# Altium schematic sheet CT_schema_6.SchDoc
size 287 x 160 mm
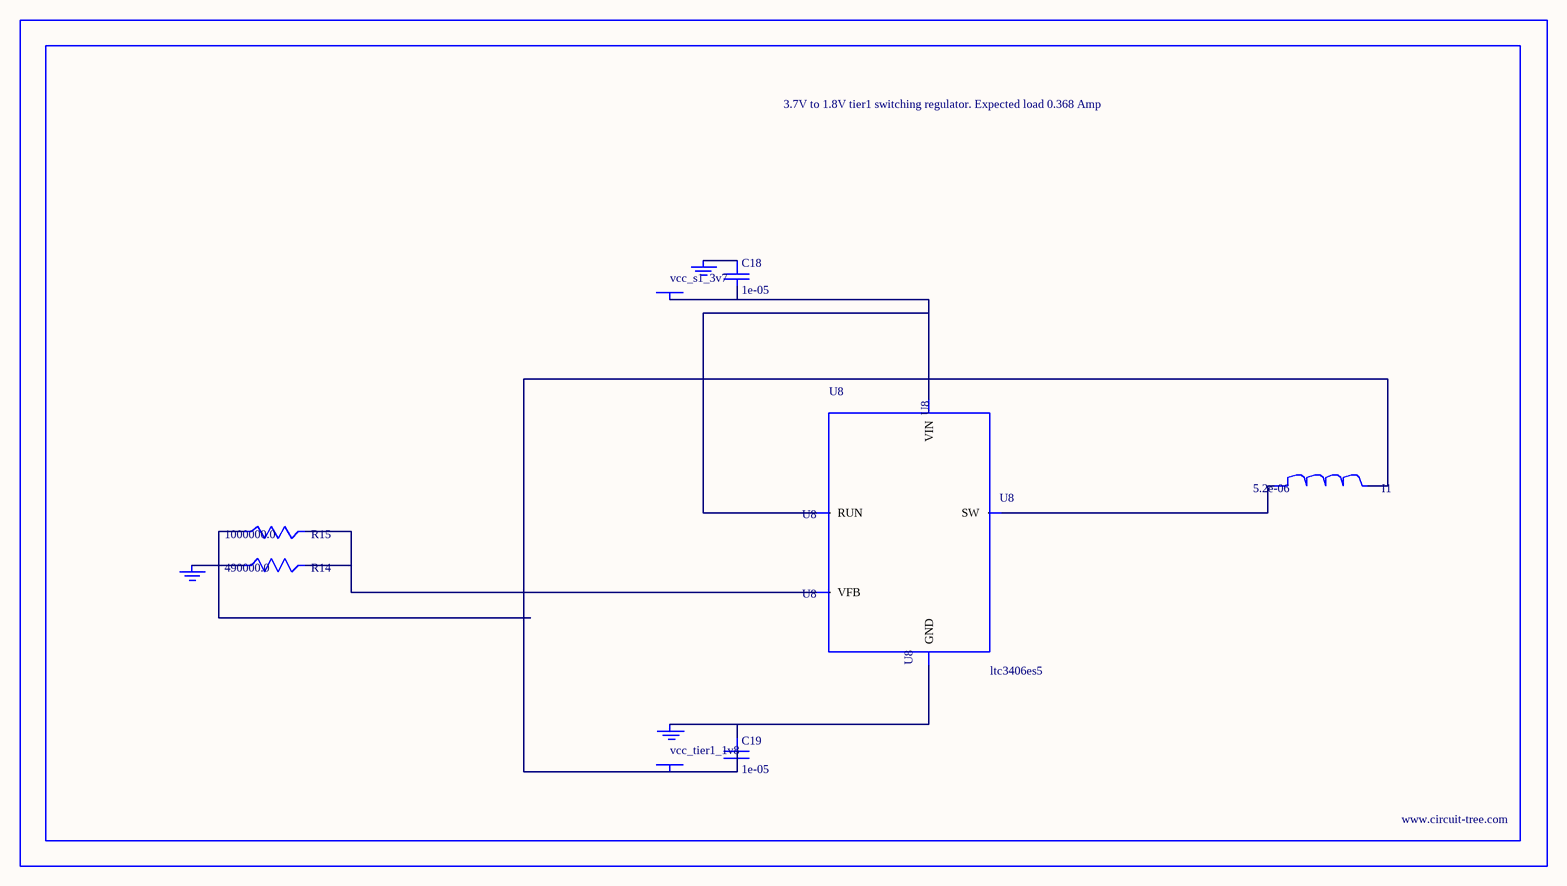
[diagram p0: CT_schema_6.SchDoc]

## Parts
BORDER5  (no value)
C18  1e-05  [C0805]
C19  1e-05  [C0805]
GND_INSTANCE_5_0  (no value)
GND_INSTANCE_5_1  (no value)
GND_INSTANCE_5_2  (no value)
I1  5.2e-06  [DR1040]
POWER_INSTANCE_5_0  vcc_tier1_1v8
POWER_INSTANCE_5_1  vcc_s1_3v7
R14  490000.0  [R0603]
R15  1000000.0  [R0603]
U8  ltc3406es5  [TSOT-23-5]

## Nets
NetC18_1: C18.1 GND_INSTANCE_5_1.0(GND)
NetC18_2: C18.2 POWER_INSTANCE_5_1.0(PWR) U8.1(RUN) U8.4(VIN)
NetC19_1: C19.1 GND_INSTANCE_5_0.0(GND) U8.2(GND)
NetC19_2: C19.2 I1.2 POWER_INSTANCE_5_0.0(PWR) R15.1
NetGND_INSTANCE_5_2_0: GND_INSTANCE_5_2.0(GND) R14.1
NetI1_1: I1.1 U8.3(SW)
NetR14_2: R14.2 R15.2 U8.5(VFB)

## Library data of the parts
BORDER5 = BORDER_PAGE5
C18 C19 = C0805C106K8RACTU
GND_INSTANCE_5_0-GND_INSTANCE_5_2 = GND
I1 = DR1040-5R2-R
POWER_INSTANCE_5_0 POWER_INSTANCE_5_1 = PWR
R14 = R14
R15 = RC0603JR-071ML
